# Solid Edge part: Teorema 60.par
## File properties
Title: Teorema 60
Author: s.pallini
Template: Normal.par
Last saved by: s.pallini
Revision: 11
Application: Solid Edge
Tipo di contenuto documento: 0
Precisione: 0,990
Document Number: 8031-60
Revision: 0
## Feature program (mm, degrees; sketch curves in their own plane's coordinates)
sketch for "unnamed Protrusion 1" plane through (0, 0, 0) normal (0, 0, 1) x-axis (1, 0, 0)
  line (-295, -190) -> (295, -190)
  line (295, -190) -> (295, 190)
  line (295, 190) -> (-295, 190)
  line (-295, 190) -> (-295, -190)
  dimension (linear) = 295
  dimension (linear) = 295
extrude "unnamed Protrusion 1" add finite 130 along +normal
sketch for "ExtrudedCutout_1" plane through (0, 0, 0) normal (0, 0, -1) x-axis (1, 0, 0)
  line (-281, -176) -> (281, -176)
  line (281, -176) -> (281, 176)
  line (281, 176) -> (-281, 176)
  line (-281, 176) -> (-281, -176)
extrude "ExtrudedCutout_1" cut finite 80 along -normal  Treatment1_DraftAngle = 20 deg
sketch for "Foro_1" plane through (0, 0, 130) normal (0, 0, 1) x-axis (1, 0, 0)
  hole centre (0, 0) bore radius 25
hole "Foro_1" diameter 50 through
sketch for "ExtrudedCutout_2" #1 plane through (0, 0, 130) normal (0, 0, 1) x-axis (1, 0, 0)
  circle centre (0, 0) radius 35
sketch for "ExtrudedCutout_2" #2 plane through (0, 0, 130) normal (0, 0, 1) x-axis (1, 0, 0)
  line (-225, -145) -> (225, -145)
  arc centre (225, -125) radius 20 from (245, -125) to (225, -145) cw
  line (245, -125) -> (245, 125)
  arc centre (225, 125) radius 20 from (225, 145) to (245, 125) cw
  line (225, 145) -> (-225, 145)
  arc centre (-225, 125) radius 20 from (-245, 125) to (-225, 145) cw
  line (-245, 125) -> (-245, -125)
  arc centre (-225, -125) radius 20 from (-245, -125) to (-225, -145) ccw
  dimension (linear) = 225
  dimension (linear) = 245
extrude "ExtrudedCutout_2" cut finite 35 along -normal  DraftAngle = 10 deg
draft "Draft_1"  Angles1 = 10 deg
fillet "Rotondo_1" radius 8
fillet "Rotondo_3" radius 10
fillet "Rotondo_4" radius 5
fillet "Rotondo_6" radius 10
fillet "Rotondo_7" radius 10
fillet "Rotondo_8" radius 6
fillet "Rotondo_10" radius 6
fillet "Rotondo_11" radius 5
sketch for "Foro_2" plane through (0, 0, 130) normal (0, 0, 1) x-axis (1, 0, 0)
  hole centre (255, -160) bore radius 6
hole "Foro_2" diameter 12 finite
sketch for "unnamed Hole 1" plane through (0, 0, 130) normal (0, 0, 1) x-axis (1, 0, 0)
  hole centre (-255, -160) bore radius 6
  dimension (linear) = 255
hole "unnamed Hole 1" finite
sketch for "Foro_4" plane through (0, 0, 130) normal (0, 0, 1) x-axis (1, 0, 0)
  hole centre (-255, -160) bore radius 8
hole "Foro_4" diameter 16 finite
sketch for "unnamed Hole 2" plane through (0, 0, 130) normal (0, 0, 1) x-axis (1, 0, 0)
  hole centre (255, -160) bore radius 8
hole "unnamed Hole 2" finite
fillet "Rotondo_13" radius 6
pattern "unnamed Pattern 1" of "Foro_2", "unnamed Hole 1"
pattern "unnamed Pattern 2" of "Foro_4", "unnamed Hole 2"
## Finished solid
Body 1: solid body, 89 faces, 174 edges, 88 vertices.
  Faces by surface: cylinder 37, plane 21, torus 14, sphere 8, cone 5, blend 4
  Edges by curve: circle 94, line 72, ellipse 8
Bounding box of the edges (mm; curved faces can reach further): 590.000 x 380.000 x 130.000, from (-295, -190, 0) to (295, 190, 130).
Cylindrical faces by radius (mm): R5 x4, R6 x14, R8 x6, R10 x12, R25 x1
Conical faces (half-angle, radius in mm at the cone's reference point): 10 deg R20 x4, 10 deg R35 x1
Toroidal faces (ring radius, tube radius in mm): R1 r5 x4, R5.4376 r10 x4, R26.7128 r8 x4, R35 r10 x1, R49.5624 r10 x1
Spherical faces by radius (mm): R6 x4, R10 x4
Planar faces by outward normal: +x 1, +y 1, +z 7, -x 1, -y 1, -z 2, oblique 8
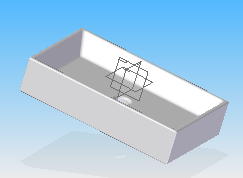
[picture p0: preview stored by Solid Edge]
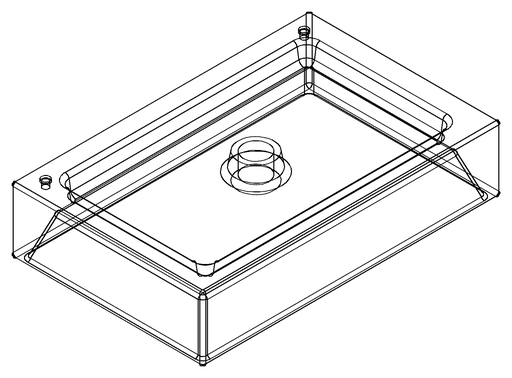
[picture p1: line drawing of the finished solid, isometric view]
